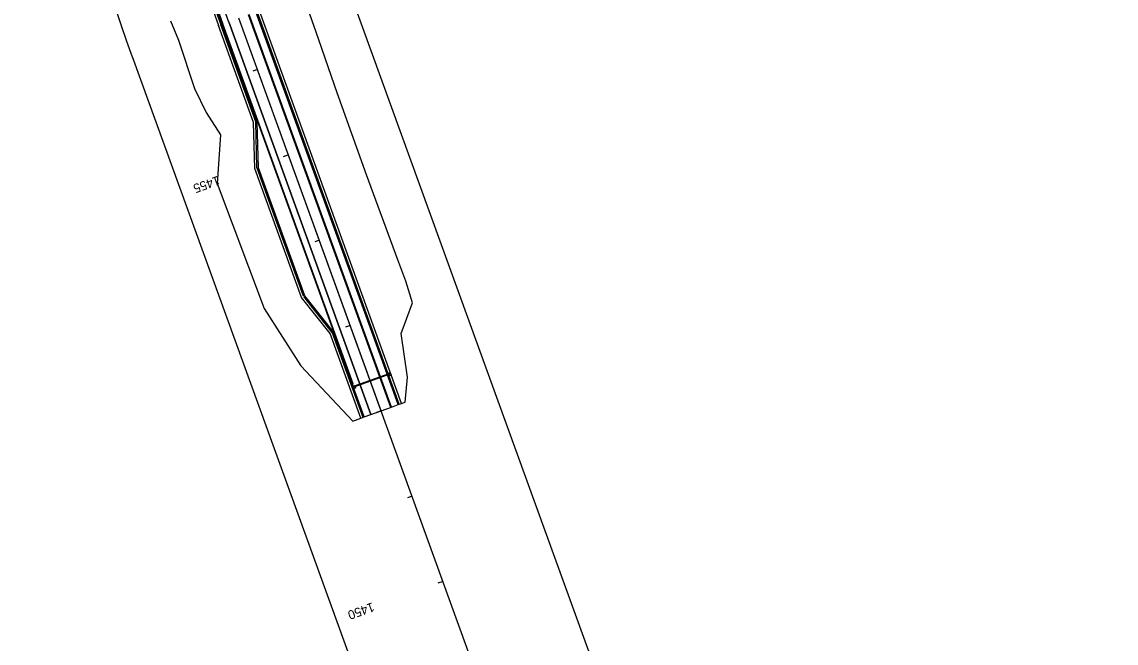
# Model space of a CAD drawing. Extents: x 21596487 to 21601936, y 8263704 to 8275922.
# Drawn here: x 21596555 to 21597761, y 8265433 to 8266117 of the extents above; entities that cross this region are included whole.
import ezdxf

# ---------------------------------------------------------------- set-up
doc = ezdxf.new("R2010")
doc.units = 0
for name, color, linetype in [('dsnGroundLineIntercept', 7, 'Continuous'), ('dsnPaintPlaceDottedLineYellow', 7, 'Continuous'), ('dsnPaintPlaceDoubleCenterLineYellow', 7, 'Continuous'), ('dsnXsROWLabelLineExist', 7, 'Continuous'), ('EdgePaved', 7, 'Continuous'), ('EdgeUnpaved', 7, 'Continuous'), ('ErosionControl', 7, 'Continuous'), ('Joints', 7, 'Continuous'), ('TC_DNC', 7, 'Continuous'), ('TC_GranularBackFill', 7, 'Continuous'), ('TC_MacadamStone', 7, 'Continuous'), ('TC_SpecialBackfill', 7, 'Continuous'), ('Wall', 7, 'Continuous')]:
    doc.layers.add(name, color=color, linetype=linetype)

msp = doc.modelspace()

# ---------------------------------------------------------------- linework, layer by layer
at = {"layer": 'dsnGroundLineIntercept'}
msp.add_lwpolyline([(21596718.6, 8266118.2), (21596727.1, 8266097.1), (21596745, 8266043.9), (21596757.6, 8266017.3), (21596773.6, 8265992.6), (21596770, 8265938.9), (21596821.7, 8265801.3), (21596862.2, 8265738.3), (21596919.3, 8265677.2), (21596928.2, 8265680.4), (21596931.9, 8265681.8), (21596939.4, 8265684.5), (21596950.7, 8265688.6), (21596962, 8265692.7), (21596969.5, 8265695.4), (21596973.3, 8265696.7), (21596977.3, 8265698.2), (21596979.8, 8265725.6), (21596972.9, 8265773.6), (21596985.2, 8265807.4), (21596978, 8265831.4), (21596969.2, 8265854.8), (21596934.6, 8265948.6), (21596902.2, 8266039), (21596892.8, 8266066.4), (21596881.6, 8266098.6), (21596864.7, 8266146.9)], dxfattribs=at)
at = {"layer": 'dsnPaintPlaceDottedLineYellow'}
for p, q in [((21596961.2, 8265692.4), (21596804.4, 8266125.1)), ((21596939.4, 8265684.5), (21596782.6, 8266117.2))]:
    msp.add_line(p, q, dxfattribs=at)
at = {"layer": 'dsnPaintPlaceDoubleCenterLineYellow'}
msp.add_lwpolyline([(21596950.7, 8265688.6), (21596793.9, 8266121.3)], dxfattribs=at)
at = {"layer": 'dsnXsROWLabelLineExist'}
for p, q in [((21597761, 8263819.8), (21596911.4, 8266163.9)), ((21597537, 8263704.3), (21596676.4, 8266078.7))]:
    msp.add_line(p, q, dxfattribs=at)
msp.add_arc((21598589.4, 8266772.1), 2034.9, 166.974, 199.9238, dxfattribs=at)
at = {"layer": 'EdgePaved'}
for points in [[(21596960, 8265727.3), (21596958.9, 8265730.2), (21596960.8, 8265730.8), (21596961.8, 8265728)], [(21596920.6, 8265713.1), (21596919.6, 8265715.9), (21596921.4, 8265716.6), (21596922.5, 8265713.7)]]:
    msp.add_lwpolyline(points, close=True, dxfattribs=at)
at = {"layer": 'EdgeUnpaved'}
for p, q in [((21596920.7, 8265714.7), (21596775.7, 8266114.7)), ((21596920, 8265718.2), (21596776.2, 8266114.9)), ((21596960.4, 8265729.1), (21596920.7, 8265714.7)), ((21596960.2, 8265729.8), (21596921.1, 8265715.6))]:
    msp.add_line(p, q, dxfattribs=at)
for radius in [1929.2, 1928.7]:
    msp.add_arc((21598589.4, 8266772.1), radius, 166.974, 199.9238, dxfattribs=at)
at = {"layer": 'ErosionControl'}
for p, q in [((21596814.4, 8266064.6), (21596809.2, 8266062.8)), ((21596848.5, 8265970.6), (21596842.7, 8265968.5)), ((21596882.6, 8265876.6), (21596877.4, 8265874.7)), ((21596916.6, 8265782.6), (21596911.5, 8265780.7)), ((21596950.7, 8265688.6), (21596945.6, 8265686.7)), ((21596984.8, 8265594.6), (21596979.6, 8265592.7)), ((21597018.9, 8265500.5), (21597013.1, 8265498.5))]:
    msp.add_line(p, q, dxfattribs=at)
at = {"layer": 'TC_DNC'}
for p, q in [((21596970.7, 8265695.8), (21596813.9, 8266128.5)), ((21596812.7, 8266007.1), (21596773.9, 8266114)), ((21596813.8, 8265956.4), (21596812.5, 8266007)), ((21596865, 8265814.9), (21596813.9, 8265956)), ((21596896.7, 8265774.8), (21596865.3, 8265814.5)), ((21596930.7, 8265681.3), (21596896.7, 8265775.3))]:
    msp.add_line(p, q, dxfattribs=at)
msp.add_arc((21598589.4, 8266772.1), 1931.1, 166.974, 199.9238, dxfattribs=at)
at = {"layer": 'TC_GranularBackFill'}
msp.add_line((21597632.1, 8263808.8), (21596793.9, 8266121.3), dxfattribs=at)
at = {"layer": 'TC_MacadamStone'}
for p, q in [((21596969.5, 8265695.4), (21596812.7, 8266128.1)), ((21596814, 8266007), (21596775.1, 8266114.5)), ((21596815.3, 8265956.5), (21596814, 8266007)), ((21596866.4, 8265815.4), (21596815.3, 8265956.5)), ((21596897.8, 8265775.8), (21596866.4, 8265815.4)), ((21596931.9, 8265681.8), (21596897.8, 8265775.8))]:
    msp.add_line(p, q, dxfattribs=at)
msp.add_arc((21598589.4, 8266772.1), 1929.9, 166.974, 199.9238, dxfattribs=at)
at = {"layer": 'TC_SpecialBackfill'}
for p, q in [((21596962, 8265692.7), (21596805.2, 8266125.4)), ((21596782.6, 8266117.2), (21596939.4, 8265684.5)), ((21596939.4, 8265684.5), (21596962, 8265692.7))]:
    msp.add_line(p, q, dxfattribs=at)
msp.add_arc((21598589.4, 8266772.1), 1921.9, 174.7312, 199.9238, dxfattribs=at)
at = {"layer": 'Wall'}
for p, q in [((21596973.3, 8265696.7), (21596816.4, 8266129.4)), ((21596810, 8266006.3), (21596771.3, 8266113.1)), ((21596811.3, 8265955.7), (21596810, 8266006.3)), ((21596862.9, 8265813.5), (21596811.3, 8265955.7)), ((21596894.3, 8265773.8), (21596862.9, 8265813.5)), ((21596928.2, 8265680.4), (21596894.3, 8265773.8))]:
    msp.add_line(p, q, dxfattribs=at)
msp.add_arc((21598589.4, 8266772.1), 1933.9, 166.974, 199.9238, dxfattribs=at)

# ---------------------------------------------------------------- texts
at = {"layer": 'Joints'}
for s, p in [('1455', (21596770.5, 8265947.7)), ('1450', (21596940.9, 8265477.6))]:
    msp.add_text(s, height=10, rotation=199.9238, dxfattribs=at).set_placement(p)

doc.saveas('drawing.dxf')
